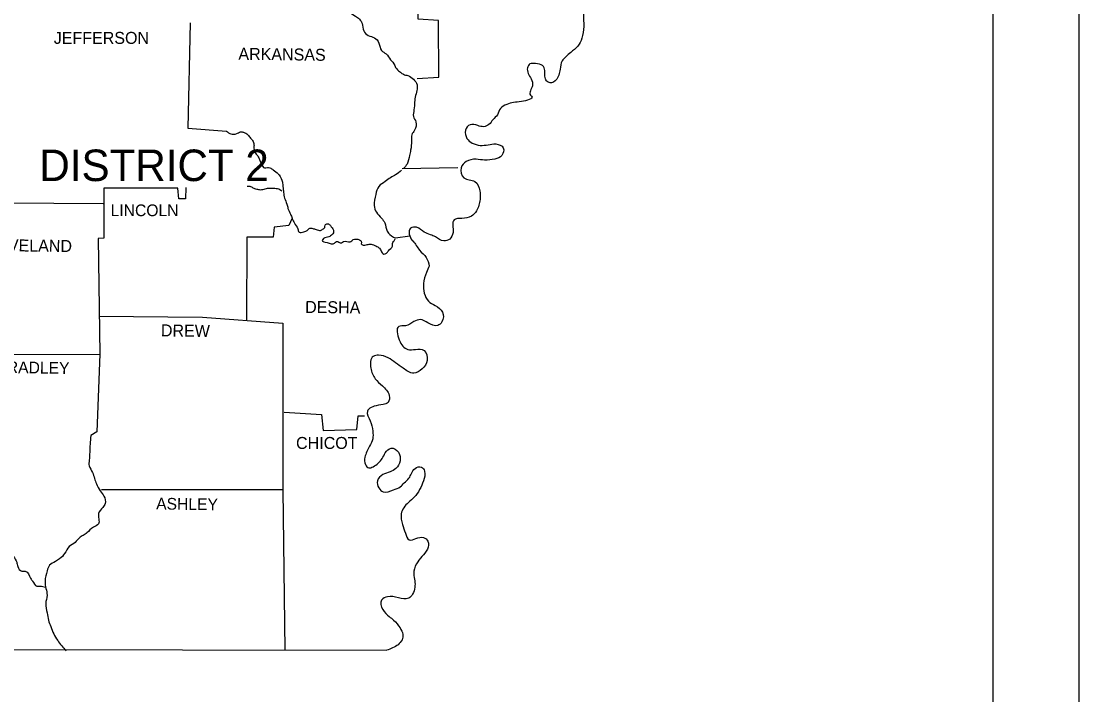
# Model space of a CAD drawing. Extents: x 61396 to 64680, y 55472 to 57605.
# Drawn here: x 64111 to 64680, y 56542 to 56905 of the extents above; entities that cross this region are included whole.
import ezdxf

# ---------------------------------------------------------------- set-up
doc = ezdxf.new("R2010")
doc.units = 0
for name, color, linetype in [('Default', 7, 'Continuous'), ('R_Border PE', 7, 'Continuous'), ('R_No Plot', 7, 'Continuous')]:
    doc.layers.add(name, color=color, linetype=linetype)

msp = doc.modelspace()

# ---------------------------------------------------------------- linework, layer by layer
at = {"layer": 'Default'}
for p, q in [((64633.61, 55511.58), (64633.61, 57566.01)), ((64315.54, 56825.26), (64345.54, 56825.71))]:
    msp.add_line(p, q, dxfattribs=at)
for points in [[(64323.64, 56873.71), (64335.34, 56874.46), (64335.19, 56904.91), (64324.24, 56905.66), (64324.84, 56965.21), (64315.39, 56966.56), (64315.09, 57006.61), (64443.04, 57007.51)], [(64201.54, 56903.56), (64200.34, 56847.01), (64221.19, 56845.36)], [(64199.24, 56815.01), (64198.99, 56808.91), (64195.54, 56808.91), (64194.94, 56814.76), (64155.04, 56814.76), (64155.09, 56806.51)], [(64101.64, 56806.81), (64154.74, 56806.51)], [(64155.09, 56806.51), (64155.19, 56787.76), (64152.04, 56787.61), (64152.94, 56725.36)], [(64256.44, 56798.56), (64254.64, 56794.51), (64246.69, 56793.76), (64246.24, 56788.36), (64231.99, 56788.36), (64231.84, 56743.51)], [(64152.49, 56745.76), (64208.14, 56745.31), (64251.34, 56742.01)], [(64251.34, 56742.01), (64251.34, 56652.31), (64252.54, 56566.06)], [(64085.14, 56725.21), (64152.94, 56725.36)], [(64152.94, 56725.36), (64151.44, 56683.66), (64148.14, 56681.56)], [(64252.09, 56694.16), (64272.19, 56692.96), (64273.09, 56684.26), (64291.24, 56684.86), (64291.99, 56692.21), (64295.44, 56692.21)], [(63757.24, 56688.31), (63757.54, 56566.96), (64307.29, 56566.06)], [(64153.84, 56652.46), (64251.34, 56652.46)]]:
    msp.add_lwpolyline(points, dxfattribs=at)
for points in [[(64433.59, 56971.21), (64430.14, 56966.86), (64425.04, 56969.56), (64425.04, 56973.16), (64425.79, 56976.91), (64423.99, 56979.31), (64420.84, 56978.26), (64420.84, 56973.61), (64420.54, 56969.11), (64419.64, 56962.66), (64421.74, 56960.71), (64426.54, 56960.11), (64429.99, 56959.21), (64432.09, 56955.76), (64431.94, 56951.56), (64430.29, 56947.51), (64427.89, 56944.21), (64424.14, 56943.01), (64421.14, 56944.96), (64419.94, 56948.86), (64418.59, 56952.31), (64416.04, 56954.86), (64413.34, 56952.01), (64412.74, 56946.76), (64412.89, 56942.26), (64412.89, 56936.11), (64416.79, 56932.06), (64419.19, 56927.41), (64418.44, 56923.21), (64415.59, 56918.26), (64414.39, 56913.91), (64413.19, 56908.06), (64413.34, 56901.61), (64412.29, 56895.31), (64410.19, 56891.11), (64406.29, 56887.66), (64403.74, 56885.41), (64401.64, 56883.16), (64400.59, 56878.66), (64399.84, 56875.51), (64396.99, 56871.76), (64394.74, 56871.46), (64392.94, 56872.96), (64392.34, 56875.51), (64392.34, 56878.06), (64391.14, 56880.61), (64387.39, 56881.66), (64384.39, 56881.51), (64383.04, 56879.41), (64384.99, 56873.56), (64385.74, 56869.81), (64384.69, 56864.71), (64385.29, 56864.11), (64379.89, 56861.26), (64375.54, 56860.81), (64371.94, 56859.76), (64368.49, 56857.51), (64366.84, 56854.21), (64364.44, 56851.51), (64362.34, 56848.96), (64359.49, 56847.76), (64356.34, 56848.36), (64352.14, 56848.81), (64349.74, 56845.81), (64350.49, 56841.46), (64353.34, 56838.91), (64357.54, 56837.71), (64361.89, 56838.01), (64366.09, 56838.46), (64369.99, 56836.36), (64369.24, 56832.31), (64365.49, 56830.36), (64359.94, 56829.76), (64355.44, 56830.21), (64350.04, 56829.01), (64347.34, 56825.56), (64348.84, 56820.31), (64354.69, 56818.21), (64357.39, 56813.26), (64357.54, 56808.61), (64355.59, 56802.46), (64352.89, 56799.61), (64347.64, 56798.41), (64343.59, 56797.66), (64342.99, 56790.76), (64341.19, 56787.31), (64338.04, 56786.26), (64333.54, 56788.51), (64330.84, 56789.56), (64327.54, 56791.06), (64323.34, 56793.61), (64320.19, 56793.16), (64321.09, 56786.56), (64321.39, 56786.26), (64324.99, 56781.31), (64328.59, 56777.41), (64330.24, 56772.76)], [(64278.19, 56922.91), (64278.64, 56916.76), (64282.24, 56915.86), (64283.74, 56914.21), (64284.49, 56910.76), (64287.04, 56909.26), (64290.49, 56907.16), (64292.59, 56905.66), (64294.09, 56903.26), (64294.99, 56899.36), (64297.39, 56896.81), (64300.69, 56895.61), (64303.09, 56892.76), (64304.59, 56888.71), (64306.99, 56886.91), (64309.39, 56883.76), (64310.59, 56882.41), (64312.69, 56878.81), (64314.79, 56877.01), (64316.29, 56875.96), (64318.69, 56875.21), (64321.69, 56873.26), (64323.64, 56870.26), (64323.64, 56868.01), (64322.89, 56864.56), (64322.29, 56860.96), (64321.99, 56856.91), (64321.69, 56853.31), (64323.04, 56850.31), (64322.29, 56845.81), (64320.79, 56843.41), (64320.64, 56840.11), (64320.19, 56835.16), (64319.59, 56832.31), (64318.24, 56827.66), (64316.29, 56825.26)], [(64221.19, 56845.36), (64223.44, 56843.86), (64226.59, 56844.01), (64228.69, 56844.91), (64230.34, 56844.76), (64232.59, 56843.41), (64234.09, 56841.61), (64235.14, 56840.26), (64235.89, 56838.16), (64235.89, 56836.21), (64236.64, 56833.51), (64237.54, 56832.46), (64238.74, 56830.51), (64239.49, 56828.71), (64239.94, 56827.51), (64241.59, 56825.56), (64243.09, 56825.71), (64244.44, 56825.56), (64246.24, 56824.51), (64248.94, 56822.41), (64249.39, 56821.81), (64251.19, 56817.91), (64251.49, 56815.51), (64251.79, 56812.36), (64252.39, 56809.36), (64253.59, 56806.06), (64254.19, 56803.81), (64255.54, 56800.66), (64256.44, 56798.56), (64257.64, 56795.86), (64259.44, 56792.86), (64260.19, 56791.06), (64262.74, 56791.21), (64264.54, 56791.96), (64265.89, 56793.16), (64267.54, 56793.01), (64269.34, 56792.41), (64271.74, 56791.96), (64273.24, 56792.86), (64273.99, 56793.46), (64274.14, 56794.81), (64275.49, 56795.56), (64276.99, 56794.51), (64278.64, 56792.11), (64278.64, 56790.61), (64278.04, 56789.71), (64276.09, 56788.51), (64273.39, 56787.61), (64272.64, 56786.56), (64275.19, 56785.36), (64279.24, 56785.06), (64280.29, 56785.96), (64282.99, 56785.21), (64284.04, 56785.96), (64287.64, 56785.81), (64289.29, 56787.01), (64292.59, 56786.86), (64293.64, 56786.11), (64293.64, 56784.76), (64296.34, 56784.16), (64298.29, 56784.61), (64300.84, 56783.86), (64303.09, 56782.66), (64304.29, 56781.01), (64305.79, 56779.21), (64307.14, 56779.66), (64308.19, 56781.01), (64310.44, 56783.41), (64310.44, 56784.91), (64311.04, 56785.96), (64311.79, 56787.46)], [(64315.24, 56824.36), (64312.09, 56821.81), (64309.39, 56820.31), (64306.54, 56818.21), (64303.09, 56815.66), (64301.44, 56811.31), (64300.54, 56805.31), (64301.74, 56801.71), (64304.44, 56798.56), (64306.24, 56796.01), (64307.59, 56791.51), (64310.89, 56788.36), (64311.94, 56787.91)], [(64232.3, 56815.82), (64232.59, 56815.81), (64234.54, 56815.36), (64236.19, 56814.46), (64237.39, 56814.16), (64239.19, 56813.86), (64240.69, 56814.01), (64243.24, 56814.61), (64244.74, 56814.61), (64247.14, 56814.61), (64248.64, 56814.46), (64250.89, 56813.26)], [(64330.24, 56772.76), (64328.74, 56769.31), (64327.09, 56763.31), (64327.54, 56758.21), (64329.79, 56753.86), (64333.39, 56751.46), (64337.29, 56748.01), (64336.99, 56742.76), (64334.74, 56740.81), (64329.49, 56742.16), (64325.44, 56743.96), (64321.99, 56742.91), (64317.34, 56740.66), (64313.89, 56740.21), (64314.04, 56733.01), (64318.69, 56727.91), (64322.74, 56727.91), (64327.39, 56727.31), (64329.04, 56721.91), (64326.34, 56717.41), (64321.84, 56715.16), (64316.14, 56717.86), (64312.09, 56720.71), (64308.04, 56723.41), (64302.94, 56724.76), (64300.09, 56724.16), (64298.74, 56717.86), (64301.14, 56712.16), (64305.04, 56708.26), (64308.64, 56703.16), (64308.04, 56699.41), (64305.34, 56698.36), (64300.54, 56697.31), (64297.69, 56695.81), (64296.94, 56694.61), (64298.44, 56689.51), (64299.79, 56683.96), (64299.79, 56679.76), (64298.14, 56675.86), (64295.59, 56669.86), (64295.89, 56665.96), (64297.69, 56664.16), (64299.94, 56664.76), (64302.94, 56666.86), (64304.89, 56669.26), (64306.54, 56672.26), (64309.69, 56674.81), (64313.59, 56672.56), (64314.49, 56667.91), (64312.24, 56663.86), (64309.09, 56662.06), (64305.19, 56660.56), (64302.34, 56657.26), (64303.09, 56653.36), (64305.34, 56651.26), (64310.89, 56652.31), (64314.64, 56653.96), (64316.74, 56656.06), (64319.29, 56658.61), (64320.64, 56661.16), (64322.59, 56663.86), (64326.04, 56664.61), (64327.69, 56662.36), (64327.09, 56657.26), (64324.99, 56652.46), (64322.14, 56648.41), (64318.99, 56645.56), (64315.09, 56639.41), (64315.84, 56633.71), (64317.34, 56629.06), (64319.44, 56625.46), (64323.04, 56626.21), (64327.09, 56626.66), (64329.49, 56624.71), (64329.19, 56620.51), (64326.19, 56616.46), (64323.34, 56612.56), (64321.84, 56607.16), (64322.44, 56603.41), (64322.44, 56599.96), (64321.24, 56596.21), (64319.14, 56594.11), (64313.59, 56594.26), (64307.74, 56594.86), (64304.59, 56593.06), (64305.19, 56587.96), (64308.64, 56584.21), (64311.04, 56582.26), (64314.49, 56578.06), (64315.99, 56574.61), (64315.54, 56571.61), (64313.44, 56569.06), (64307.29, 56566.06)], [(64148.14, 56681.56), (64147.69, 56676.91), (64147.54, 56672.56), (64147.24, 56668.36), (64147.24, 56665.21), (64149.04, 56661.76), (64150.09, 56658.46), (64151.14, 56655.61), (64153.24, 56651.86), (64155.19, 56649.01), (64155.79, 56644.96), (64154.59, 56642.86), (64152.34, 56639.71), (64152.19, 56634.01), (64149.49, 56632.21), (64146.04, 56629.21), (64144.09, 56627.86), (64141.99, 56626.51), (64139.74, 56624.11), (64136.44, 56621.86), (64134.04, 56618.11), (64131.34, 56615.26), (64129.09, 56613.76), (64125.94, 56611.81), (64124.59, 56608.81), (64123.54, 56603.26), (64123.99, 56599.21), (64124.59, 56595.61), (64123.84, 56591.11), (64124.59, 56586.16), (64125.34, 56582.26), (64126.54, 56578.81), (64128.19, 56574.91), (64130.29, 56571.31), (64134.79, 56565.76)], [(63998.59, 56646.91), (64000.99, 56648.56), (64003.24, 56649.46), (64005.49, 56649.01), (64007.89, 56648.71), (64009.99, 56649.01), (64012.69, 56648.56), (64014.94, 56647.21), (64017.49, 56646.16), (64020.04, 56646.16), (64022.29, 56646.16), (64024.24, 56644.81), (64027.84, 56644.96), (64030.84, 56646.16), (64033.84, 56647.06), (64037.89, 56647.51), (64041.49, 56644.96), (64044.04, 56642.86), (64046.14, 56640.46), (64047.64, 56637.76), (64049.29, 56636.26), (64051.99, 56635.21), (64054.09, 56634.76), (64056.64, 56634.01), (64057.99, 56633.41), (64059.19, 56630.56), (64061.14, 56626.66), (64064.89, 56625.31), (64069.54, 56627.11), (64073.29, 56628.16), (64075.99, 56629.06), (64077.64, 56629.66), (64079.14, 56629.81), (64078.69, 56630.11), (64080.49, 56630.56), (64082.14, 56629.36), (64083.19, 56627.71), (64084.99, 56625.31), (64086.64, 56623.21), (64088.29, 56622.46), (64089.94, 56623.36), (64092.19, 56622.61), (64094.14, 56621.86), (64096.39, 56621.26), (64098.34, 56621.11), (64100.89, 56620.51), (64102.84, 56619.46), (64104.64, 56618.41), (64106.44, 56616.46), (64108.24, 56613.46), (64108.84, 56611.06), (64110.94, 56608.66), (64112.89, 56608.66), (64115.74, 56604.76), (64116.79, 56603.26), (64119.04, 56600.56), (64120.69, 56600.56), (64123.84, 56599.96)]]:
    msp.add_spline(points, degree=3, dxfattribs=at)
at = {"layer": 'R_Border PE'}
msp.add_line((64312, 56787.88), (64319.76, 56788.99), dxfattribs=at)
at = {"layer": 'R_No Plot'}
msp.add_lwpolyline([(61396.28, 57605.48), (64679.67, 57605.48), (64679.67, 55472.15), (61396.28, 55472.15)], close=True, dxfattribs=at)

# ---------------------------------------------------------------- texts
at = {"layer": 'Default'}
for s, height, p in [('JEFFERSON', 6.45, (64128.19, 56892.31)), ('DISTRICT 2', 16.95, (64120.45, 56818.49)), ('LINCOLN', 6.3, (64158.79, 56799.61)), ('CHICOT', 6.45, (64258.54, 56674.36))]:
    msp.add_text(s, height=height, dxfattribs=at).set_placement(p)
for s, height, rotation, p in [('ARKANSAS', 6.449, 359.2678, (64227.49, 56883.78)), ('CLEVELAND', 6.451, 359.3376, (64086.68, 56780.9)), ('DESHA', 6.449, 359.3704, (64263.39, 56747.55)), ('DREW', 6.449, 359.2258, (64185.79, 56734.96)), ('BRADLEY', 6.299, 359.1449, (64097.29, 56715.31)), ('ASHLEY', 6.301, 359.2361, (64183.24, 56641.81))]:
    msp.add_text(s, height=height, rotation=rotation, dxfattribs=at).set_placement(p)

doc.saveas('drawing.dxf')
